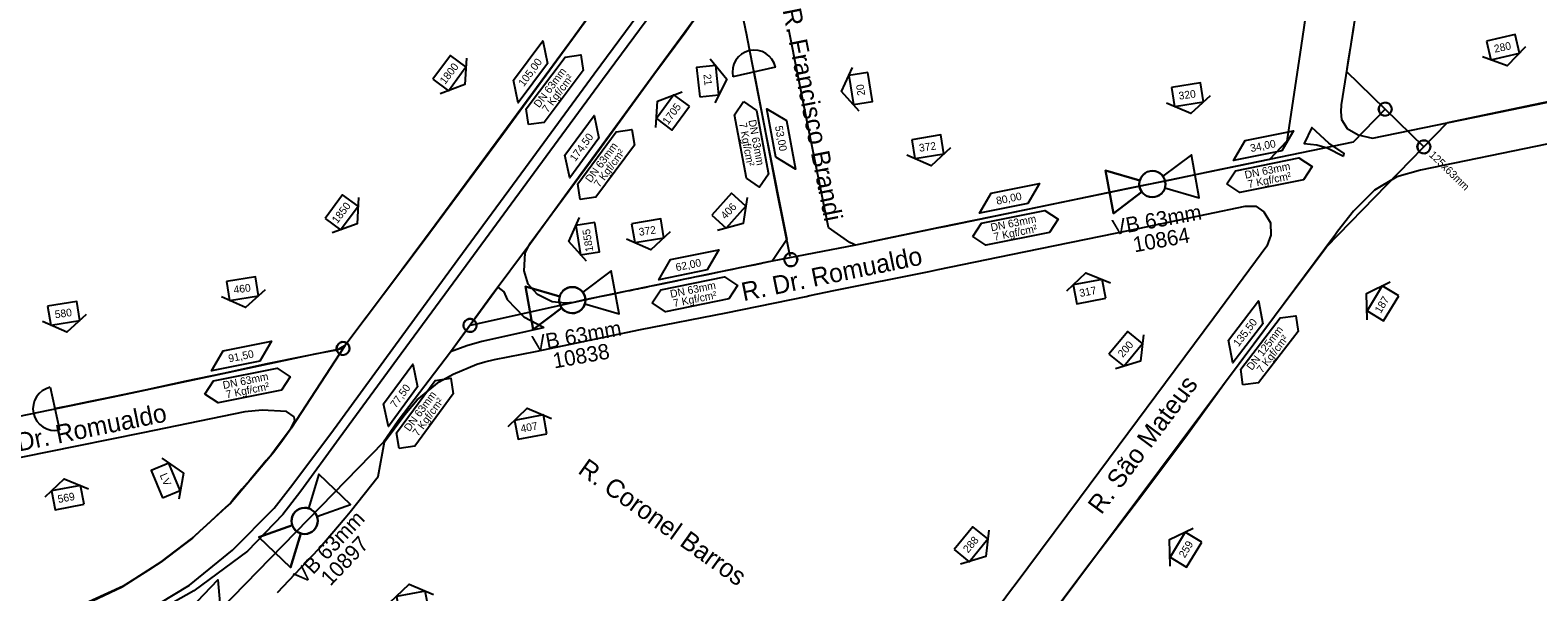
# Model space of a CAD drawing. Extents: x 656692 to 673945, y 7585994 to 7599066.
# Drawn here: x 669543 to 670131, y 7591839 to 7592058 of the extents above; entities that cross this region are included whole.
import ezdxf

# ---------------------------------------------------------------- set-up
doc = ezdxf.new("R2010")
doc.units = 0
for name, color, linetype in [('FORMATO', 7, 'Continuous'), ('LOGRADOURO', 7, 'Continuous'), ('LOGRADOURO_TEXTO', 7, 'Continuous'), ('NUM_REF', 7, 'Continuous'), ('SIMBOLO', 7, 'Continuous'), ('TEXTO', 7, 'Continuous'), ('TUBO_PEAD_GN_125', 7, 'Continuous'), ('TUBO_PEAD_GN_63', 7, 'Continuous'), ('VALVULA_PEAD_63', 7, 'Continuous')]:
    doc.layers.add(name, color=color, linetype=linetype)

# ---------------------------------------------------------------- blocks, each defined once
blk = doc.blocks.new('INTERLIGACAO_5')
at = {"layer": 'SIMBOLO'}
blk.add_circle((0, 0), 1.28, dxfattribs=at)
for start, end in [(0, 180), (180, 0)]:
    blk.add_arc((0, 0), 1.28, start, end, dxfattribs=at)
blk = doc.blocks.new('VALVULA_PEAD_DN_9')
at = {"layer": 'VALVULA_PEAD_63'}
for points in [[(-1.14, 0.57), (-4.25, 2.13), (-4.25, -2.13), (-1.14, -0.57)], [(-1.14, -0.57), (-4.25, -2.13), (-4.25, 2.13), (-1.14, 0.57)], [(1.14, -0.57), (4.25, -2.13), (4.25, 2.13), (1.14, 0.57)], [(1.14, -0.57), (4.25, -2.13), (4.25, 2.13), (1.14, 0.57)]]:
    blk.add_lwpolyline(points, dxfattribs=at)
blk.add_circle((0, 0), 1.28, dxfattribs=at)
for start, end in [(90, 270), (153.4349, 206.5651), (270, 90), (0, 26.5651), (333.4349, 0)]:
    blk.add_arc((0, 0), 1.28, start, end, dxfattribs=at)
blk = doc.blocks.new('NUM_REF_1')
at = {"layer": 'NUM_REF'}
blk.add_lwpolyline([(-4.3125, 0.9375), (0, 3.75), (4.3125, 0.9375)], dxfattribs=at)
blk.add_lwpolyline([(2.875, -1.875), (2.875, 1.875), (-2.875, 1.875), (-2.875, -1.875)], close=True, dxfattribs=at)

msp = doc.modelspace()

# ---------------------------------------------------------------- linework, layer by layer
at = {"layer": 'LOGRADOURO'}
for p, q in [((669626.48, 7591908.86), (669586.77, 7591900.63)), ((669633.3, 7591909.53), (669626.48, 7591908.86)), ((669642.86, 7591908.96), (669633.3, 7591909.53)), ((669645.76, 7591906.9), (669642.86, 7591908.96)), ((669641.21, 7591897.81), (669644.52, 7591902.28)), ((669644.52, 7591902.28), (669646.07, 7591905.37)), ((669646.07, 7591905.37), (669645.76, 7591906.9)), ((669586.77, 7591900.63), (669560.92, 7591895.46)), ((669637.8, 7591893.2), (669641.21, 7591897.81)), ((669560.92, 7591895.46), (669500.38, 7591883.19)), ((669620.83, 7591873.1), (669637.8, 7591893.2)), ((669605.9, 7591859.41), (669620.83, 7591873.1)), ((669593.87, 7591850.25), (669605.9, 7591859.41)), ((669578.71, 7591840.55), (669593.87, 7591850.25)), ((669557.74, 7591830.71), (669578.71, 7591840.55))]:
    msp.add_line(p, q, dxfattribs=at)
for points in [[(670163.5, 7592216.05), (670130.6, 7592208.69), (670091.68, 7592200), (670084.01, 7592191.87), (670082.07, 7592189.77), (670078.34, 7592185.04), (670072.15, 7592144.83), (670064.84, 7592097.22), (670059.01, 7592057.93), (670054.41, 7592028.54), (670054.19, 7592025.83), (670054.54, 7592022.85), (670056.73, 7592019.3), (670061.01, 7592016.93), (670066.54, 7592015.59), (670116.01, 7592025.7)], [(669459.79, 7591891.13), (669525.83, 7591904.5), (669578.28, 7591915.3), (669653.98, 7591931.45), (669661.62, 7591932.86), (669663.09, 7591933.21), (669665.55, 7591934.7), (669695.76, 7591974.74), (669727.46, 7592017.52), (669754.41, 7592054.38), (669784.3, 7592095.47), (669786.61, 7592101.29), (669786.07, 7592105.33), (669782.71, 7592110.4), (669778.05, 7592113.09), (669776.37, 7592113.4), (669773.03, 7592113.16), (669768.83, 7592112.32), (669729.93, 7592104.37), (669688.75, 7592096.07), (669633.45, 7592085.1)], [(670046.38, 7592103.68), (670038.75, 7592051.68), (670033.21, 7592014.39), (670026.41, 7592007.24), (669974.76, 7591996.59), (669933.23, 7591988.06), (669899.42, 7591981.05), (669896.65, 7591980.5), (669864.9, 7591973.86), (669864.09, 7591974.26), (669862.6, 7591974.86), (669854.27, 7591980.69), (669846.11, 7592021.27), (669838.88, 7592057.97)], [(669581.93, 7591827.22), (669604.97, 7591841.22), (669621.71, 7591854.83), (669637.93, 7591871.22), (669644.42, 7591879.48), (669660.06, 7591900.3), (669684.33, 7591933.57), (669709.69, 7591968.25), (669736.05, 7592004.11), (669762.87, 7592040.67), (669789.56, 7592076.83)], [(669792.75, 7592074.49), (669766.11, 7592038.37), (669739.44, 7592002.04), (669712.95, 7591965.9), (669687.53, 7591931.4), (669663.38, 7591898.42), (669648.36, 7591877.87), (669641.39, 7591868.83), (669627.58, 7591854.49), (669606.58, 7591839), (669582.43, 7591825.39)], [(670116.01, 7592025.7), (670171.03, 7592037)], [(670055.34, 7592008.53), (670055.48, 7592009.54), (670049.56, 7592013.62), (670042.96, 7592019.74), (670039.98, 7592013.55), (670044.85, 7592013.04), (670048.88, 7592011.85), (670055.34, 7592008.53)], [(670134.64, 7592013.26), (670085.32, 7592003.09), (670076.1, 7592000.43), (670067.33, 7591995.34), (670060.31, 7591988.26), (670059.13, 7591987.1), (670052.98, 7591979.22), (670052.1, 7591978.06), (670024.13, 7591940.47), (669975.42, 7591875.15), (669951.2, 7591842.74), (669926.87, 7591810.12), (669925.76, 7591808.48), (669925.04, 7591806.5), (669925.41, 7591803.62), (669927.72, 7591801.12), (669930.58, 7591799.11), (670036.36, 7591722.83)], [(669639.28, 7591838.38), (669655.23, 7591855.29), (669665.67, 7591867.49), (669667.68, 7591869.77), (669678.53, 7591883.53), (669681, 7591897.12), (669688.95, 7591907.82), (669693.84, 7591913.52), (669702.43, 7591920.46), (669707.88, 7591923.55), (669717.13, 7591927.45), (669720.17, 7591928.35), (669724.03, 7591929.2), (669739.95, 7591932.4), (669780.98, 7591940.88), (669814.4, 7591947.42), (669845.62, 7591953.85), (669847.04, 7591954.19), (669856.39, 7591956.11), (669893.59, 7591963.59), (669897.09, 7591964.32), (669925.57, 7591970.22), (669971.97, 7591979.66), (670016.87, 7591989.09), (670021.02, 7591989.07), (670024.23, 7591986.78), (670026.85, 7591982.51), (670026.9, 7591977.69), (670025.32, 7591973.44), (670004.72, 7591945.51), (669952.24, 7591874.97), (669927.21, 7591841.34), (669925.78, 7591839.46), (669903.34, 7591809.24)], [(669706.85, 7591932.19), (669725.23, 7591957.51), (669727.57, 7591955.59), (669728.89, 7591952.59), (669735.41, 7591945.89), (669743.12, 7591941.91), (669743.01, 7591941.6), (669731.36, 7591939.01), (669719.02, 7591936.24), (669713.19, 7591934.52), (669706.85, 7591932.19)]]:
    msp.add_lwpolyline(points, dxfattribs=at)
msp.add_lwpolyline([(669814.41, 7592078.64), (669816.38, 7592079), (669817.9, 7592077.16), (669822.26, 7592055.88), (669822.55, 7592054.47), (669830.07, 7592015.82), (669838.05, 7591976.07), (669834.05, 7591970.05), (669833.21, 7591968.88), (669832.34, 7591967.56), (669758.57, 7591952.32), (669754.75, 7591951.47), (669751.53, 7591951.19), (669746.44, 7591951.71), (669740.8, 7591954.62), (669737.15, 7591958.66), (669735.54, 7591963.76), (669736, 7591970.77), (669737.91, 7591974.68), (669763.63, 7592009.49), (669786.18, 7592040.35), (669798.65, 7592057.25), (669800.66, 7592060.13)], close=True, dxfattribs=at)
at = {"layer": 'SIMBOLO'}
for points in [[(669744.7, 7592044.76), (669733.17, 7592029.38), (669731.37, 7592038.23), (669742.89, 7592053.61)], [(669833.73, 7592008.18), (669830.2, 7592027.07), (669837.94, 7592022.41), (669841.47, 7592003.52)], [(669764.71, 7592015.58), (669753.32, 7592000.1), (669751.44, 7592008.94), (669762.84, 7592024.41)], [(670031.19, 7592010.64), (670012.36, 7592006.81), (670016.9, 7592014.62), (670035.73, 7592018.45)], [(669932.05, 7591990.13), (669913.22, 7591986.3), (669917.75, 7591994.11), (669936.59, 7591997.94)], [(669806.99, 7591964.2), (669788.15, 7591960.37), (669792.69, 7591968.18), (669811.52, 7591972.01)], [(670023.77, 7591943.18), (670012.05, 7591927.95), (670010.36, 7591936.82), (670022.07, 7591952.06)], [(669632.41, 7591928.6), (669613.58, 7591924.78), (669618.11, 7591932.59), (669636.95, 7591936.41)], [(669693.97, 7591918.52), (669682.57, 7591903.05), (669680.69, 7591911.88), (669692.09, 7591927.36)], [(669616.79, 7591834.28), (669603.53, 7591820.37), (669602.79, 7591829.37), (669616.05, 7591843.28)]]:
    msp.add_lwpolyline(points, close=True, dxfattribs=at)
for points in [[(669737.24, 7592020.85), (669736.36, 7592026.97), (669751.51, 7592047.18), (669757.63, 7592048.06), (669758.51, 7592041.93), (669743.37, 7592021.72), (669737.24, 7592020.85)], [(669821.16, 7592029.84), (669826.27, 7592026.35), (669830.9, 7592001.53), (669827.41, 7591996.42), (669822.3, 7591999.92), (669817.66, 7592024.74), (669821.16, 7592029.84)], [(669757.46, 7591991.6), (669756.53, 7591997.72), (669771.5, 7592018.05), (669777.62, 7592018.98), (669778.55, 7592012.86), (669763.57, 7591992.53), (669757.46, 7591991.6)], [(670009.73, 7591997.73), (670013.14, 7592002.89), (670037.89, 7592007.92), (670043.05, 7592004.51), (670039.63, 7591999.35), (670014.89, 7591994.32), (670009.73, 7591997.73)], [(669910.58, 7591977.22), (669914, 7591982.37), (669938.74, 7591987.41), (669943.9, 7591983.99), (669940.49, 7591978.83), (669915.74, 7591973.8), (669910.58, 7591977.22)], [(669785.52, 7591951.29), (669788.94, 7591956.45), (669813.68, 7591961.48), (669818.84, 7591958.06), (669815.42, 7591952.9), (669790.68, 7591947.87), (669785.52, 7591951.29)], [(670016.01, 7591919.36), (670015.21, 7591925.5), (670030.6, 7591945.51), (670036.74, 7591946.32), (670037.54, 7591940.18), (670022.15, 7591920.16), (670016.01, 7591919.36)], [(669610.94, 7591915.69), (669614.36, 7591920.85), (669639.1, 7591925.88), (669644.26, 7591922.47), (669640.85, 7591917.31), (669616.1, 7591912.28), (669610.94, 7591915.69)], [(669686.71, 7591894.55), (669685.78, 7591900.66), (669700.76, 7591920.99), (669706.87, 7591921.92), (669707.8, 7591915.81), (669692.83, 7591895.47), (669686.71, 7591894.55)]]:
    msp.add_lwpolyline(points, dxfattribs=at)
at = {"layer": 'TUBO_PEAD_GN_125'}
for points in [[(670143.9, 7592031.52), (670129.43, 7592028.59), (670095.85, 7592021.61)], [(669932.81, 7591818.29), (669954.72, 7591847.66), (669975.29, 7591874.66), (669993.37, 7591898.73), (670008.85, 7591919.98), (670026.01, 7591943.01), (670048.61, 7591973.17), (670095.78, 7592021.55)]]:
    msp.add_lwpolyline(points, dxfattribs=at)
at = {"layer": 'TUBO_PEAD_GN_63'}
for p, q in [((669833.61, 7592043.26), (669817.01, 7592039.56)), ((670086.65, 7592012.17), (670056.45, 7592041.61)), ((669550.59, 7591918.38), (669554.16, 7591901.75))]:
    msp.add_line(p, q, dxfattribs=at)
for points in [[(669806.35, 7592067.88), (669788.63, 7592043.8), (669770.24, 7592018.7), (669752.43, 7591994.4), (669737.98, 7591974.55), (669722.29, 7591953.38), (669706.82, 7591932.07), (669686.37, 7591905.3), (669680.71, 7591896.98), (669602.04, 7591816.35)], [(669762.24, 7592065.17), (669754.79, 7592054.88), (669738.94, 7592033.2), (669718.4, 7592005.42), (669700.81, 7591981.65), (669683.34, 7591958.27), (669665.53, 7591934.58), (669644.6, 7591902.42), (669638.1, 7591893.78), (669636.89, 7591892.11), (669634.87, 7591889.78), (669631.83, 7591886.17), (669628.46, 7591882.15), (669625.43, 7591878.59), (669622.31, 7591874.88), (669620.94, 7591873.22), (669619.04, 7591871.47), (669615.34, 7591868.07), (669612.96, 7591865.92), (669611.28, 7591864.37), (669609.14, 7591862.4), (669606.06, 7591859.55), (669603.03, 7591857.24), (669599.19, 7591854.32), (669594.29, 7591850.59), (669593.81, 7591850.22), (669592.34, 7591849.27), (669588.92, 7591847.07), (669583.65, 7591843.72), (669579.07, 7591840.83), (669555.17, 7591829.83)], [(670059.2, 7592059.2), (670058.49, 7592054.9), (670057.85, 7592050.53), (670057.02, 7592045.27), (670056.61, 7592042.59), (670056.45, 7592041.61)], [(669839.35, 7591969.43), (669834.37, 7591993.86), (669825.31, 7592041.41)], [(670071.55, 7592026.89), (670059.02, 7592014.05), (670026.28, 7592007.24), (670004.15, 7592002.68), (669987.59, 7591999.22), (669971.27, 7591995.92), (669949.49, 7591991.4), (669924.36, 7591986.21), (669897.66, 7591980.7), (669874.65, 7591975.9), (669864.88, 7591973.85), (669832.32, 7591967.55), (669830.94, 7591967.28), (669829.09, 7591966.88), (669827.59, 7591966.58), (669825.19, 7591966.09), (669822.36, 7591965.51), (669819.63, 7591964.94), (669816.85, 7591964.36), (669814.77, 7591963.94), (669812.16, 7591963.39), (669809.88, 7591962.92), (669807.45, 7591962.42), (669804.89, 7591961.89), (669802.73, 7591961.45), (669800.31, 7591960.95), (669797.55, 7591960.38), (669794.92, 7591959.83), (669787.24, 7591958.24), (669785.83, 7591957.95), (669784.51, 7591957.68), (669783.08, 7591957.38), (669781.78, 7591957.12), (669780.87, 7591956.93), (669779.92, 7591956.73), (669778.88, 7591956.51), (669777.8, 7591956.29), (669776.76, 7591956.08), (669775.61, 7591955.84), (669774.4, 7591955.59), (669769.78, 7591954.63), (669764.96, 7591953.65), (669754.9, 7591951.53), (669714.42, 7591942.54)], [(669664.86, 7591933.55), (669635.28, 7591927.51), (669618.28, 7591923.83), (669603.71, 7591920.77), (669587.65, 7591917.33), (669575.87, 7591914.79), (669571.33, 7591913.87), (669565.56, 7591912.68), (669558.82, 7591911.3), (669552.84, 7591910.09)]]:
    msp.add_lwpolyline(points, dxfattribs=at)
for centre, start, end in [((669825.31, 7592041.41), 12.54512, 192.54512), ((669552.38, 7591910.06), 102.12642, 282.12642)]:
    msp.add_arc(centre, 8.51, start, end, dxfattribs=at)

# ---------------------------------------------------------------- block references
at = {"layer": 'FORMATO'}
for p, xscale, yscale, rotation in [((670117.48, 7592051.09), 2, 2.0000000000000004, -166.66750398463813), ((669706.38, 7592040.95), 1.9999999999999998, 1.9999999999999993, -126.37652921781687), ((669807.2, 7592037.78), 2, 2, -83.87575993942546), ((669866.83, 7592034.94), 1.9999999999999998, 1.9999999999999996, 98.82224989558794), ((669793.61, 7592025.6), 2, 2, 53.67593436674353), ((669994.43, 7592032.54), 2, 1.9999999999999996, -170.6909186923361), ((669893.1, 7592012.22), 2, 1.9999999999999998, -170.69091869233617), ((669664.28, 7591986.65), 1.9999999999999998, 1.9999999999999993, -126.37652921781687), ((669815.41, 7591987.28), 2, 2, -131.8670646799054), ((669760.35, 7591976.36), 1.9999999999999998, 1.9999999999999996, 98.82224989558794), ((669783.75, 7591979.45), 2.0000000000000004, 1.9999999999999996, -170.69091869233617), ((669625.63, 7591956.88), 2, 1.9999999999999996, -170.69091869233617), ((669956.17, 7591955.73), 2, 2, 10.671463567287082), ((670070.65, 7591951.14), 1.9999999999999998, 1.9999999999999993, 58.759156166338), ((669555.85, 7591947.25), 2, 1.9999999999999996, -170.69091869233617), ((669970.31, 7591933.4), 2, 2, -129.5839750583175), ((669738.11, 7591902.84), 2, 2, 10.671463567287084), ((669595.69, 7591882.01), 1.9999999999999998, 2.0000000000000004, -67.45554694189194), ((669557.46, 7591875.37), 2, 2, 10.671463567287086), ((669909.92, 7591857.18), 2, 2, -129.5839750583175), ((669993.77, 7591855.06), 1.9999999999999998, 1.9999999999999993, 58.759156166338), ((669692.01, 7591834.17), 2, 2, 10.671463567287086)]:
    msp.add_blockref('NUM_REF_1', p, dxfattribs=dict(at, xscale=xscale, yscale=yscale, rotation=rotation))
at = {"layer": 'SIMBOLO', "xscale": 2, "yscale": 2}
for p, rotation in [((670071.55, 7592026.89), -14.764722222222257), ((670086.65, 7592012.17), -14.764722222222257), ((669839.59, 7591968.18), -14.764722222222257), ((669714.42, 7591942.54), 23.35885686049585), ((669664.86, 7591933.54), -14.764722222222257)]:
    msp.add_blockref('INTERLIGACAO_5', p, dxfattribs=dict(at, rotation=rotation))
at = {"layer": 'VALVULA_PEAD_63'}
for p, xscale, yscale, rotation in [((669980.71, 7591997.67), 3.999999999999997, 3.999999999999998, 10.298316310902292), ((669754.32, 7591952.39), 3.9999999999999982, 3.9999999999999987, 10.298295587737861), ((669649.89, 7591866.27), 3.999999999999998, 3.999999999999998, 46.29275120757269)]:
    msp.add_blockref('VALVULA_PEAD_DN_9', p, dxfattribs=dict(at, xscale=xscale, yscale=yscale, rotation=rotation))

# ---------------------------------------------------------------- texts
for s, height, rotation, p in [('280', 3, 11.82817, (670114.36, 7592048.91)), ('1800', 3, 52.11915, (669704.7, 7592036.36)), ('21', 3, 276.12424, (669805.49, 7592040.44)), ('20', 3, 98.82225, (669868.67, 7592032.37)), ('320', 3, 7.80476, (669991.17, 7592030.58)), ('1705', 3, 53.67593, (669791.7, 7592020.61)), ('372', 3, 7.80476, (669889.84, 7592010.26)), ('125x63mm', 3, 315.72132, (670088.46, 7592008.78)), ('1850', 3, 52.11915, (669662.61, 7591982.05)), ('406', 3, 46.62861, (669814.1, 7591983.71)), ('VB 63mm', 6, 10.29832, (669965.65, 7591977.66)), ('1855', 3, 98.82225, (669762.55, 7591971.49)), ('372', 3, 7.80476, (669780.49, 7591977.48)), ('10864', 6, 10.29832, (669973.72, 7591970.99)), ('460', 3, 7.80476, (669622.37, 7591954.92)), ('317', 3, 10.67146, (669952.51, 7591953.6)), ('580', 3, 7.80476, (669552.59, 7591945.29)), ('187', 3, 58.75916, (670069.8, 7591947)), ('VB 63mm', 6, 10.2983, (669739.25, 7591932.37)), ('10838', 6, 10.2983, (669747.33, 7591925.71)), ('200', 3, 48.9117, (669969.14, 7591929.78)), ('407', 3, 10.67146, (669734.45, 7591900.71)), ('LV', 3, 292.54445, (669593.27, 7591884.14)), ('569', 3, 10.67146, (669553.81, 7591873.23)), ('VB 63mm', 6, 46.29275, (669649.47, 7591841.22)), ('10897', 6, 46.29275, (669659.91, 7591840.57)), ('288', 3, 48.9117, (669908.76, 7591853.56)), ('259', 3, 58.75916, (669993.33, 7591851.58))]:
    msp.add_text(s, height=height, rotation=rotation).set_placement(p)
at = {"layer": 'LOGRADOURO_TEXTO'}
for s, rotation, p in [('R. Francisco Brandi', 281.22727, (669836.35, 7592065.59)), ('R. Dr. Romualdo', 11.55502, (669821.14, 7591951.98)), ('R. São Mateus', 53.34706, (669960.76, 7591868.4)), ('R. Dr. Romualdo', 11.51206, (669526.27, 7591890.83)), ('R. Coronel Barros', 324.61046, (669756.1, 7591885.15))]:
    msp.add_text(s, height=7.2, rotation=rotation, dxfattribs=at).set_placement(p)
at = {"layer": 'TEXTO'}
for s, rotation, p in [('105,00', 53.15536, (669735.39, 7592035.47)), ('DN 63mm', 53.15536, (669741.38, 7592027.2)), ('7 Kgf/cm²', 53.15536, (669744.7, 7592025.3)), ('7 Kgf/cm²', 280.58673, (669819.39, 7592021.34)), ('DN 63mm', 280.58673, (669823.04, 7592022.5)), ('53,00', 280.58673, (669833.4, 7592020.17)), ('174,50', 53.63111, (669755.48, 7592006.21)), ('DN 63mm', 53.63111, (669761.54, 7591997.99)), ('34,00', 11.49062, (670019.21, 7592010.12)), ('7 Kgf/cm²', 53.63111, (669764.88, 7591996.11)), ('DN 63mm', 11.49062, (670017.04, 7591999.73)), ('7 Kgf/cm²', 11.49062, (670018.26, 7591996.1)), ('80,00', 11.49062, (669920.07, 7591989.6)), ('DN 63mm', 11.49062, (669917.9, 7591979.21)), ('7 Kgf/cm²', 11.49062, (669919.12, 7591975.58)), ('62,00', 11.49062, (669795, 7591963.67)), ('DN 63mm', 11.49062, (669792.84, 7591953.28)), ('7 Kgf/cm²', 11.49062, (669794.05, 7591949.65)), ('135,50', 52.43921, (670014.34, 7591934.01)), ('DN 125mm', 52.43921, (670019.52, 7591924.75)), ('7 Kgf/cm²', 52.43921, (670023.53, 7591923.72)), ('91,50', 11.49062, (669620.42, 7591928.08)), ('DN 63mm', 11.49062, (669618.26, 7591917.69)), ('7 Kgf/cm²', 11.49062, (669619.47, 7591914.06)), ('77,50', 53.63111, (669685.43, 7591910.09)), ('DN 63mm', 53.63111, (669690.8, 7591900.94)), ('7 Kgf/cm²', 53.63111, (669694.13, 7591899.06))]:
    msp.add_text(s, height=3, rotation=rotation, dxfattribs=at).set_placement(p)

doc.saveas('drawing.dxf')
